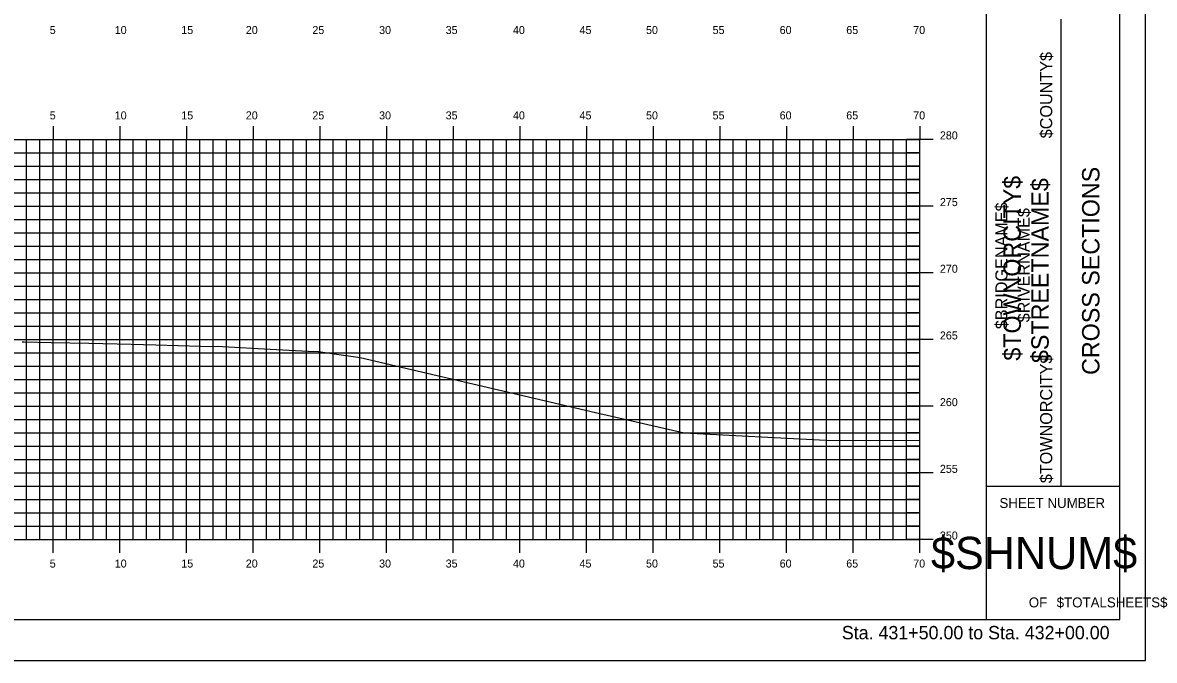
# Model space of a CAD drawing. Extents: x 1168600 to 1177589, y 610178 to 611246.
# Drawn here: x 1176075.1 to 1176160, y 610900.5 to 610948.3 of the extents above; entities that cross this region are included whole.
import ezdxf

# ---------------------------------------------------------------- set-up
doc = ezdxf.new("R2010")
doc.units = 0
for name, color, linetype in [('_Construction', 7, 'Continuous'), ('_Station Equation', 7, 'Continuous'), ('H_V ANNOTATION', 7, 'Continuous'), ('MAJOR', 7, 'Continuous'), ('MINOR', 7, 'Continuous')]:
    doc.layers.add(name, color=color, linetype=linetype)

msp = doc.modelspace()

# ---------------------------------------------------------------- linework, layer by layer
at = {"layer": '_Construction'}
for p, q in [((1176147.42, 610903.599), (1176147.42, 611008.599)), ((1176157.42, 610903.599), (1176157.42, 611008.599)), ((1176153.011, 610913.599), (1176153.011, 610948.599)), ((1176147.42, 610913.599), (1176157.42, 610913.599)), ((1175997.42, 610903.596), (1176157.42, 610903.596))]:
    msp.add_line(p, q, dxfattribs=at)
msp.add_lwpolyline([(1175989.326, 610900.537), (1176159.326, 610900.537), (1176159.326, 611010.537), (1175989.326, 611010.537)], close=True, dxfattribs=at)
at = {"layer": '_Station Equation'}
for points in [[(1176075.105, 610924.423), (1176075.159, 610924.424), (1176075.243, 610924.424), (1176077.272, 610924.378), (1176080.109, 610924.318), (1176083.272, 610924.236), (1176085.113, 610924.188), (1176088.486, 610924.101), (1176090.117, 610924.06), (1176093.701, 610923.863), (1176095.121, 610923.784), (1176096.538, 610923.73), (1176097.323, 610923.699), (1176098.506, 610923.524), (1176100.44, 610923.237), (1176118.083, 610919.116), (1176124.738, 610917.599), (1176135.361, 610917.051), (1176142.419, 610917.027)], [(1176075.105, 610924.423), (1176075.159, 610924.424), (1176075.243, 610924.424), (1176077.272, 610924.378), (1176080.109, 610924.318), (1176083.273, 610924.236), (1176085.113, 610924.188), (1176088.487, 610924.101), (1176090.117, 610924.06), (1176093.702, 610923.863), (1176095.121, 610923.784), (1176096.538, 610923.73), (1176097.323, 610923.699), (1176098.506, 610923.524), (1176100.44, 610923.237), (1176118.084, 610919.116), (1176124.738, 610917.599), (1176135.361, 610917.051), (1176142.419, 610917.027)]]:
    msp.add_lwpolyline(points, dxfattribs=at)
at = {"layer": 'MAJOR'}
for p, q in [((1176077.419, 610940.598), (1176077.419, 610939.596)), ((1176082.419, 610940.598), (1176082.419, 610939.596)), ((1176087.419, 610940.598), (1176087.419, 610939.596)), ((1176092.419, 610940.598), (1176092.419, 610939.596)), ((1176097.419, 610940.598), (1176097.419, 610939.596)), ((1176102.419, 610940.598), (1176102.419, 610939.596)), ((1176107.419, 610940.598), (1176107.419, 610939.596)), ((1176112.419, 610940.598), (1176112.419, 610939.596)), ((1176117.419, 610940.598), (1176117.419, 610939.596)), ((1176122.419, 610940.598), (1176122.419, 610939.596)), ((1176127.419, 610940.598), (1176127.419, 610939.596)), ((1176132.419, 610940.598), (1176132.419, 610939.596)), ((1176137.419, 610940.598), (1176137.419, 610939.596)), ((1176142.419, 610940.598), (1176142.419, 610939.596)), ((1176002.419, 610939.596), (1176142.419, 610939.596)), ((1176002.419, 610939.596), (1176142.419, 610939.596)), ((1176077.419, 610909.596), (1176077.419, 610939.596)), ((1176082.419, 610909.596), (1176082.419, 610939.596)), ((1176087.419, 610909.596), (1176087.419, 610939.596)), ((1176092.419, 610909.596), (1176092.419, 610939.596)), ((1176097.419, 610909.596), (1176097.419, 610939.596)), ((1176102.419, 610909.596), (1176102.419, 610939.596)), ((1176107.419, 610909.596), (1176107.419, 610939.596)), ((1176112.419, 610909.596), (1176112.419, 610939.596)), ((1176117.419, 610909.596), (1176117.419, 610939.596)), ((1176122.419, 610909.596), (1176122.419, 610939.596)), ((1176127.419, 610909.596), (1176127.419, 610939.596)), ((1176132.419, 610909.596), (1176132.419, 610939.596)), ((1176137.419, 610909.596), (1176137.419, 610939.596)), ((1176143.421, 610939.596), (1176141.417, 610939.596)), ((1176142.419, 610909.596), (1176142.419, 610939.596)), ((1176142.419, 610909.596), (1176142.419, 610939.596)), ((1176002.419, 610934.596), (1176142.419, 610934.596)), ((1176143.421, 610934.596), (1176141.417, 610934.596)), ((1176002.419, 610929.596), (1176142.419, 610929.596)), ((1176143.421, 610929.596), (1176141.417, 610929.596)), ((1176002.419, 610924.596), (1176142.419, 610924.596)), ((1176143.421, 610924.596), (1176141.417, 610924.596)), ((1176002.419, 610919.596), (1176142.419, 610919.596)), ((1176143.421, 610919.596), (1176141.417, 610919.596)), ((1176002.419, 610914.596), (1176142.419, 610914.596)), ((1176143.421, 610914.596), (1176141.417, 610914.596)), ((1176002.419, 610909.596), (1176142.419, 610909.596)), ((1176002.419, 610909.596), (1176142.419, 610909.596)), ((1176077.419, 610908.594), (1176077.419, 610909.596)), ((1176082.419, 610908.594), (1176082.419, 610909.596)), ((1176087.419, 610908.594), (1176087.419, 610909.596)), ((1176092.419, 610908.594), (1176092.419, 610909.596)), ((1176097.419, 610908.594), (1176097.419, 610909.596)), ((1176102.419, 610908.594), (1176102.419, 610909.596)), ((1176107.419, 610908.594), (1176107.419, 610909.596)), ((1176112.419, 610908.594), (1176112.419, 610909.596)), ((1176117.419, 610908.594), (1176117.419, 610909.596)), ((1176122.419, 610908.594), (1176122.419, 610909.596)), ((1176127.419, 610908.594), (1176127.419, 610909.596)), ((1176132.419, 610908.594), (1176132.419, 610909.596)), ((1176137.419, 610908.594), (1176137.419, 610909.596)), ((1176143.421, 610909.596), (1176141.417, 610909.596)), ((1176142.419, 610908.594), (1176142.419, 610909.596))]:
    msp.add_line(p, q, dxfattribs=at)
at = {"layer": 'MINOR'}
for p, q in [((1176075.419, 610909.596), (1176075.419, 610939.596)), ((1176076.419, 610909.596), (1176076.419, 610939.596)), ((1176078.419, 610909.596), (1176078.419, 610939.596)), ((1176079.419, 610909.596), (1176079.419, 610939.596)), ((1176080.419, 610909.596), (1176080.419, 610939.596)), ((1176081.419, 610909.596), (1176081.419, 610939.596)), ((1176083.419, 610909.596), (1176083.419, 610939.596)), ((1176084.419, 610909.596), (1176084.419, 610939.596)), ((1176085.419, 610909.596), (1176085.419, 610939.596)), ((1176086.419, 610909.596), (1176086.419, 610939.596)), ((1176088.419, 610909.596), (1176088.419, 610939.596)), ((1176089.419, 610909.596), (1176089.419, 610939.596)), ((1176090.419, 610909.596), (1176090.419, 610939.596)), ((1176091.419, 610909.596), (1176091.419, 610939.596)), ((1176093.419, 610909.596), (1176093.419, 610939.596)), ((1176094.419, 610909.596), (1176094.419, 610939.596)), ((1176095.419, 610909.596), (1176095.419, 610939.596)), ((1176096.419, 610909.596), (1176096.419, 610939.596)), ((1176098.419, 610909.596), (1176098.419, 610939.596)), ((1176099.419, 610909.596), (1176099.419, 610939.596)), ((1176100.419, 610909.596), (1176100.419, 610939.596)), ((1176101.419, 610909.596), (1176101.419, 610939.596)), ((1176103.419, 610909.596), (1176103.419, 610939.596)), ((1176104.419, 610909.596), (1176104.419, 610939.596)), ((1176105.419, 610909.596), (1176105.419, 610939.596)), ((1176106.419, 610909.596), (1176106.419, 610939.596)), ((1176108.419, 610909.596), (1176108.419, 610939.596)), ((1176109.419, 610909.596), (1176109.419, 610939.596)), ((1176110.419, 610909.596), (1176110.419, 610939.596)), ((1176111.419, 610909.596), (1176111.419, 610939.596)), ((1176113.419, 610909.596), (1176113.419, 610939.596)), ((1176114.419, 610909.596), (1176114.419, 610939.596)), ((1176115.419, 610909.596), (1176115.419, 610939.596)), ((1176116.419, 610909.596), (1176116.419, 610939.596)), ((1176118.419, 610909.596), (1176118.419, 610939.596)), ((1176119.419, 610909.596), (1176119.419, 610939.596)), ((1176120.419, 610909.596), (1176120.419, 610939.596)), ((1176121.419, 610909.596), (1176121.419, 610939.596)), ((1176123.419, 610909.596), (1176123.419, 610939.596)), ((1176124.419, 610909.596), (1176124.419, 610939.596)), ((1176125.419, 610909.596), (1176125.419, 610939.596)), ((1176126.419, 610909.596), (1176126.419, 610939.596)), ((1176128.419, 610909.596), (1176128.419, 610939.596)), ((1176129.419, 610909.596), (1176129.419, 610939.596)), ((1176130.419, 610909.596), (1176130.419, 610939.596)), ((1176131.419, 610909.596), (1176131.419, 610939.596)), ((1176133.419, 610909.596), (1176133.419, 610939.596)), ((1176134.419, 610909.596), (1176134.419, 610939.596)), ((1176135.419, 610909.596), (1176135.419, 610939.596)), ((1176136.419, 610909.596), (1176136.419, 610939.596)), ((1176138.419, 610909.596), (1176138.419, 610939.596)), ((1176139.419, 610909.596), (1176139.419, 610939.596)), ((1176140.419, 610909.596), (1176140.419, 610939.596)), ((1176141.419, 610909.596), (1176141.419, 610939.596)), ((1176002.419, 610938.596), (1176142.419, 610938.596)), ((1176142.419, 610938.596), (1176141.417, 610938.596)), ((1176002.419, 610937.596), (1176142.419, 610937.596)), ((1176142.419, 610937.596), (1176141.417, 610937.596)), ((1176002.419, 610936.596), (1176142.419, 610936.596)), ((1176142.419, 610936.596), (1176141.417, 610936.596)), ((1176002.419, 610935.596), (1176142.419, 610935.596)), ((1176142.419, 610935.596), (1176141.417, 610935.596)), ((1176002.419, 610933.596), (1176142.419, 610933.596)), ((1176142.419, 610933.596), (1176141.417, 610933.596)), ((1176002.419, 610932.596), (1176142.419, 610932.596)), ((1176142.419, 610932.596), (1176141.417, 610932.596)), ((1176002.419, 610931.596), (1176142.419, 610931.596)), ((1176142.419, 610931.596), (1176141.417, 610931.596)), ((1176002.419, 610930.596), (1176142.419, 610930.596)), ((1176142.419, 610930.596), (1176141.417, 610930.596)), ((1176002.419, 610928.596), (1176142.419, 610928.596)), ((1176142.419, 610928.596), (1176141.417, 610928.596)), ((1176002.419, 610927.596), (1176142.419, 610927.596)), ((1176142.419, 610927.596), (1176141.417, 610927.596)), ((1176002.419, 610926.596), (1176142.419, 610926.596)), ((1176142.419, 610926.596), (1176141.417, 610926.596)), ((1176002.419, 610925.596), (1176142.419, 610925.596)), ((1176142.419, 610925.596), (1176141.417, 610925.596)), ((1176002.419, 610923.596), (1176142.419, 610923.596)), ((1176142.419, 610923.596), (1176141.417, 610923.596)), ((1176002.419, 610922.596), (1176142.419, 610922.596)), ((1176142.419, 610922.596), (1176141.417, 610922.596)), ((1176002.419, 610921.596), (1176142.419, 610921.596)), ((1176142.419, 610921.596), (1176141.417, 610921.596)), ((1176002.419, 610920.596), (1176142.419, 610920.596)), ((1176142.419, 610920.596), (1176141.417, 610920.596)), ((1176002.419, 610918.596), (1176142.419, 610918.596)), ((1176142.419, 610918.596), (1176141.417, 610918.596)), ((1176002.419, 610917.596), (1176142.419, 610917.596)), ((1176142.419, 610917.596), (1176141.417, 610917.596)), ((1176002.419, 610916.596), (1176142.419, 610916.596)), ((1176142.419, 610916.596), (1176141.417, 610916.596)), ((1176002.419, 610915.596), (1176142.419, 610915.596)), ((1176142.419, 610915.596), (1176141.417, 610915.596)), ((1176002.419, 610913.596), (1176142.419, 610913.596)), ((1176142.419, 610913.596), (1176141.417, 610913.596)), ((1176002.419, 610912.596), (1176142.419, 610912.596)), ((1176142.419, 610912.596), (1176141.417, 610912.596)), ((1176002.419, 610911.596), (1176142.419, 610911.596)), ((1176142.419, 610911.596), (1176141.417, 610911.596)), ((1176002.419, 610910.596), (1176142.419, 610910.596)), ((1176142.419, 610910.596), (1176141.417, 610910.596))]:
    msp.add_line(p, q, dxfattribs=at)

# ---------------------------------------------------------------- texts
at = {"layer": '_Construction'}
for s, height, rotation, p in [('$COUNTY$', 0.9072, 90, (1176152.34, 610939.678)), ('CROSS SECTIONS', 1.30428, 90, (1176155.884, 610921.938)), ('$TOWNORCITY$', 1.30428, 90, (1176149.992, 610923.007)), ('$STREETNAME$', 1.30428, 90, (1176152.079, 610922.827)), ('$BRIDGENAME$', 0.90716, 90, (1176148.986, 610925.367)), ('$RIVERNAME$', 0.90716, 90, (1176150.663, 610925.882)), ('$TOWNORCITY$', 0.90716, 90, (1176152.34, 610913.82)), ('SHEET NUMBER', 0.74527, 360, (1176148.385, 610911.963)), ('$SHNUM$', 2.4194, 360, (1176143.253, 610907.379)), ('OF', 0.7453, 360, (1176150.587, 610904.509)), ('$TOTALSHEETS$', 0.74527, 360, (1176152.676, 610904.509))]:
    msp.add_text(s, height=height, rotation=rotation, dxfattribs=at).set_placement(p)
at = {"layer": 'H_V ANNOTATION'}
for s, height, p in [('5', 0.6, (1176077.171, 610947.496)), ('10', 0.6, (1176082.045, 610947.496)), ('15', 0.6, (1176087.037, 610947.496)), ('20', 0.6, (1176091.873, 610947.496)), ('25', 0.6, (1176096.865, 610947.496)), ('30', 0.6, (1176101.868, 610947.496)), ('35', 0.6, (1176106.86, 610947.496)), ('40', 0.6, (1176111.906, 610947.496)), ('45', 0.6, (1176116.898, 610947.496)), ('50', 0.6, (1176121.884, 610947.496)), ('55', 0.6, (1176126.876, 610947.496)), ('60', 0.6, (1176131.906, 610947.496)), ('65', 0.6, (1176136.898, 610947.496)), ('70', 0.6, (1176141.922, 610947.496)), ('5', 0.6, (1176077.171, 610941.096)), ('10', 0.6, (1176082.045, 610941.096)), ('15', 0.6, (1176087.037, 610941.096)), ('20', 0.6, (1176091.873, 610941.096)), ('25', 0.6, (1176096.865, 610941.096)), ('30', 0.6, (1176101.868, 610941.096)), ('35', 0.6, (1176106.86, 610941.096)), ('40', 0.6, (1176111.906, 610941.096)), ('45', 0.6, (1176116.898, 610941.096)), ('50', 0.6, (1176121.884, 610941.096)), ('55', 0.6, (1176126.876, 610941.096)), ('60', 0.6, (1176131.906, 610941.096)), ('65', 0.6, (1176136.898, 610941.096)), ('70', 0.6, (1176141.922, 610941.096)), ('280', 0.6, (1176143.919, 610939.596)), ('275', 0.6, (1176143.919, 610934.596)), ('270', 0.6, (1176143.919, 610929.596)), ('265', 0.6, (1176143.919, 610924.596)), ('260', 0.6, (1176143.919, 610919.596)), ('255', 0.6, (1176143.919, 610914.596)), ('250', 0.6, (1176143.919, 610909.596)), ('5', 0.6, (1176077.171, 610907.496)), ('10', 0.6, (1176082.045, 610907.496)), ('15', 0.6, (1176087.037, 610907.496)), ('20', 0.6, (1176091.873, 610907.496)), ('25', 0.6, (1176096.865, 610907.496)), ('30', 0.6, (1176101.868, 610907.496)), ('35', 0.6, (1176106.86, 610907.496)), ('40', 0.6, (1176111.906, 610907.496)), ('45', 0.6, (1176116.898, 610907.496)), ('50', 0.6, (1176121.884, 610907.496)), ('55', 0.6, (1176126.876, 610907.496)), ('60', 0.6, (1176131.906, 610907.496)), ('65', 0.6, (1176136.898, 610907.496)), ('70', 0.6, (1176141.922, 610907.496)), ('Sta. 431+50.00 to Sta. 432+00.00', 1.0002, (1176136.565, 610902.116))]:
    msp.add_text(s, height=height, dxfattribs=at).set_placement(p)

doc.saveas('drawing.dxf')
